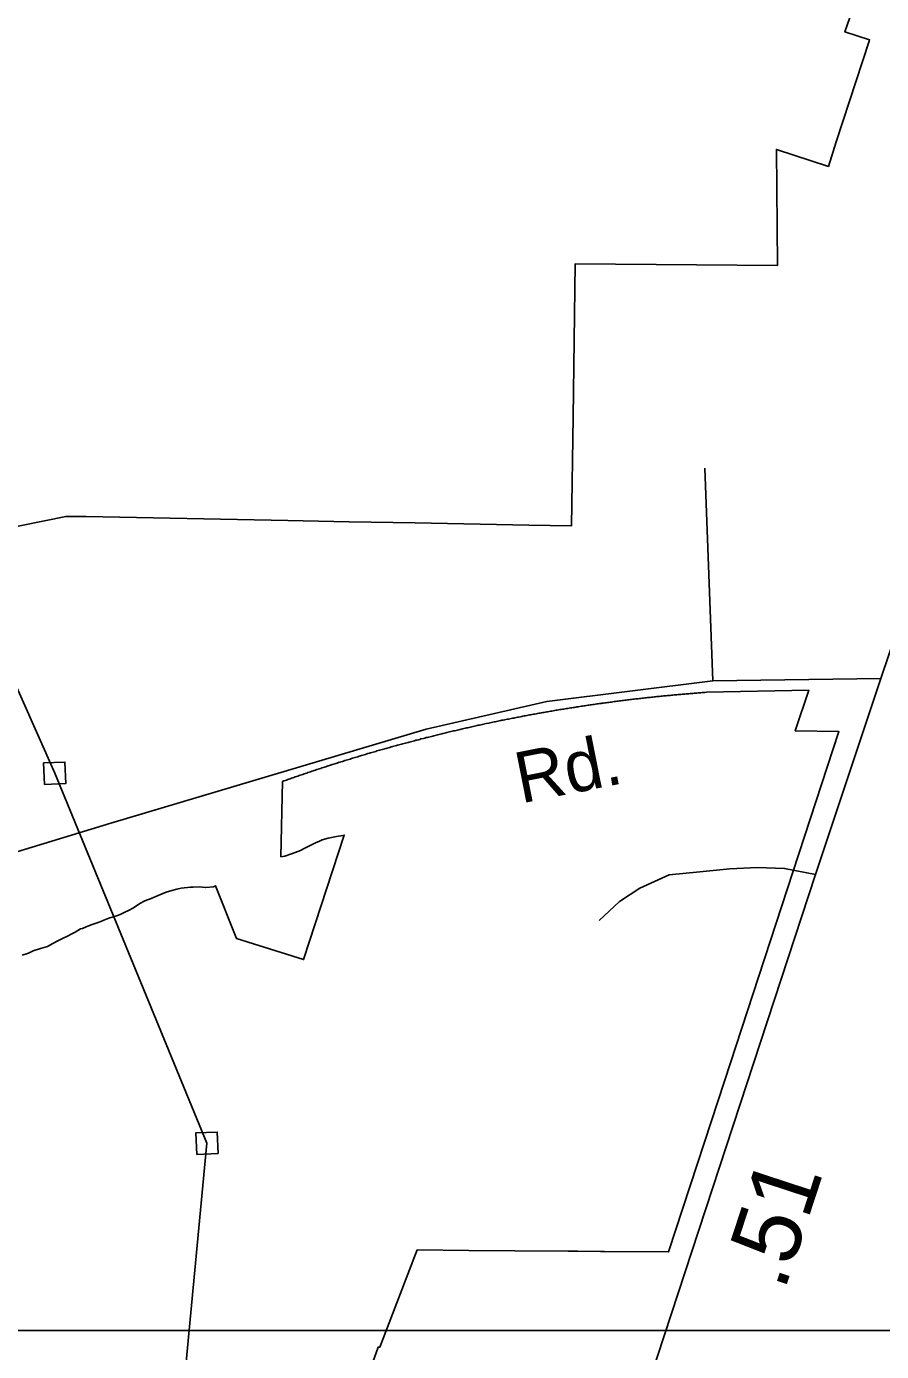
# Model space of a CAD drawing. Extents: x 2220236 to 2384410, y 720751 to 894131.
# Drawn here: x 2349968 to 2351563, y 785007 to 787479 of the extents above; entities that cross this region are included whole.
import ezdxf

# ---------------------------------------------------------------- set-up
doc = ezdxf.new("R2010")
doc.units = 0
doc.layers.add('Default', color=7, linetype='Continuous')

msp = doc.modelspace()

# ---------------------------------------------------------------- linework, layer by layer
at = {"layer": 'Default'}
msp.add_line((2351248.7, 786258.7), (2351233.6, 786655.1), dxfattribs=at)
for points in [[(2329807.7, 816974.9), (2370566.3, 816974.8), (2370566.3, 785046.7), (2329807.6, 785046.7), (2329807.7, 816974.9)], [(2350869.9, 782495.5), (2350436.8, 783070.4), (2350101.5, 783514.1), (2350174, 784150.7), (2350246.2, 784777.5), (2350304.8, 785395.9), (2350020.7, 786086.2), (2349800.8, 786581.5), (2349578.7, 787102.6), (2349360.6, 787617.7), (2349132.2, 788154.8), (2348908.1, 788664.1), (2348869.5, 789213.3), (2348832.1, 789830.7), (2348791.1, 790408), (2348767.9, 790843.5), (2348707.3, 791564.5), (2348681.9, 792186.1)], [(2351562, 786262.8), (2351799.1, 786963.7), (2351989.4, 787562.6), (2352125.4, 787964.9), (2352181.4, 788133.8), (2352264.4, 788402.1), (2352402.7, 788810.6), (2352509.2, 789143.1), (2352616.4, 789474.3), (2352724.5, 789807.5), (2352833.5, 790143.2), (2353000.4, 790646)], [(2349752.8, 786506.5), (2350041.2, 786565.4), (2350075.2, 786564.9), (2350079.2, 786564.9), (2350456, 786557.6), (2350570.2, 786555.4), (2350693.5, 786553.1), (2350905.5, 786549), (2350984.8, 786547.5), (2350988.2, 786750.3), (2350992, 787036.6), (2351369, 787033.2), (2351367.2, 787250.1), (2351464.2, 787218.4), (2351479, 787264.2), (2351540.5, 787452.1), (2351541.2, 787454.5), (2351495.2, 787469.2), (2351533, 787579.1)], [(2349752.8, 786506.5), (2350041.2, 786565.4), (2350075.2, 786564.9), (2350079.2, 786564.9), (2350456, 786557.6), (2350570.2, 786555.4), (2350693.5, 786553.1), (2350905.5, 786549), (2350984.8, 786547.5), (2350988.2, 786750.3), (2350992, 787036.6), (2351369, 787033.2), (2351367.2, 787250.1), (2351464.2, 787218.4), (2351479, 787264.2), (2351540.5, 787452.1), (2351541.2, 787454.5), (2351495.2, 787469.2), (2351533, 787579.1)], [(2347439.5, 785590.9), (2348148.9, 785589.9), (2348375.2, 785586.7), (2348691.9, 785588.9), (2348756.3, 785590.8), (2348812.8, 785598.7), (2348858.9, 785604.4), (2349766.1, 785883.8), (2350125.4, 785993), (2350713.5, 786168.5), (2350938.9, 786219.8), (2351248.7, 786258.7), (2351562, 786262.8)], [(2349423.6, 779733.7), (2349826, 780958.2), (2350004.8, 781494.8), (2350260.7, 782295.8), (2350506.4, 783037.3), (2351081.3, 784803.5), (2351440.4, 785897.5), (2351562, 786262.8)], [(2350697.2, 785196.8), (2350793.2, 785196.1), (2350879, 785195.4), (2350978.5, 785194.7), (2350996.8, 785194.6), (2351039, 785194.2), (2351046.5, 785194.2), (2351166, 785193.3), (2351233, 785398.1), (2351270.2, 785511.9), (2351483.8, 786164), (2351402.5, 786165.4), (2351427.5, 786241.4), (2351237, 786237.2), (2351233.8, 786236.9), (2351231.2, 786236.8), (2351228.8, 786236.6), (2351226.2, 786236.4), (2351223.8, 786236.2), (2351221.2, 786236), (2351218.8, 786235.8), (2351216.2, 786235.6), (2351213.8, 786235.4), (2351211.2, 786235.2), (2351208.8, 786235), (2351206.2, 786234.8), (2351203.8, 786234.6), (2351201.2, 786234.4), (2351199, 786234.2), (2351196.5, 786234), (2351194, 786233.8), (2351191.5, 786233.6), (2351189, 786233.3), (2351186.5, 786233.1), (2351184, 786232.9), (2351181.5, 786232.7), (2351179, 786232.4), (2351176.5, 786232.2), (2351174, 786232), (2351171.5, 786231.8), (2351169, 786231.5), (2351166.5, 786231.2), (2351164, 786231.1), (2351161.5, 786230.8), (2351159, 786230.6), (2351156.5, 786230.3), (2351154, 786230.1), (2351151.5, 786229.8), (2351149, 786229.6), (2351146.5, 786229.3), (2351144, 786229.1), (2351141.8, 786228.8), (2351139.2, 786228.6), (2351136.8, 786228.2), (2351134.2, 786228), (2351131.8, 786227.8), (2351129.2, 786227.5), (2351126.8, 786227.2), (2351124.2, 786226.9), (2351121.8, 786226.6), (2351119.2, 786226.4), (2351116.8, 786226.1), (2351114.2, 786225.8), (2351111.8, 786225.6), (2351109.2, 786225.2), (2351106.8, 786224.9), (2351104.2, 786224.7), (2351102, 786224.4), (2351099.5, 786224.1), (2351097, 786223.8), (2351094.5, 786223.5), (2351092, 786223.2), (2351089.5, 786222.9), (2351087, 786222.6), (2351084.5, 786222.3), (2351082, 786222), (2351079.5, 786221.7), (2351077, 786221.4), (2351074.5, 786221.1), (2351072, 786220.8), (2351069.5, 786220.4), (2351067.2, 786220.1), (2351064.8, 786219.8), (2351062.2, 786219.4), (2351059.8, 786219.1), (2351057.2, 786218.8), (2351054.8, 786218.4), (2351052.2, 786218.1), (2351049.8, 786217.8), (2351047.2, 786217.4), (2351044.8, 786217.1), (2351042.2, 786216.8), (2351040, 786216.4), (2351037.5, 786216.1), (2351035, 786215.8), (2351032.5, 786215.4), (2351030, 786215.1), (2351027.5, 786214.7), (2351025, 786214.3), (2351022.5, 786214), (2351020, 786213.6), (2351017.5, 786213.2), (2351015.2, 786212.9), (2351012.8, 786212.5), (2351010.2, 786212.2), (2351007.8, 786211.8), (2351005.2, 786211.4), (2351002.8, 786211.1), (2351000.2, 786210.7), (2350997.8, 786210.3), (2350995.2, 786209.9), (2350993, 786209.5), (2350990.5, 786209.1), (2350988, 786208.8), (2350985.5, 786208.4), (2350983, 786208), (2350980.5, 786207.6), (2350978, 786207.2), (2350975.5, 786206.8), (2350973.2, 786206.4), (2350970.8, 786206), (2350968.2, 786205.6), (2350965.8, 786205.2), (2350963.2, 786204.8), (2350960.8, 786204.4), (2350958.2, 786203.9), (2350956, 786203.6), (2350953.5, 786203.1), (2350951, 786202.7), (2350948.5, 786202.3), (2350946, 786201.9), (2350943.5, 786201.4), (2350941, 786201), (2350938.8, 786200.6), (2350936.2, 786200.2), (2350933.8, 786199.8), (2350931.2, 786199.3), (2350928.8, 786198.9), (2350926.2, 786198.4), (2350923.8, 786198), (2350921.5, 786197.6), (2350919, 786197.1), (2350916.5, 786196.7), (2350914, 786196.2), (2350911.5, 786195.8), (2350909, 786195.3), (2350906.8, 786194.9), (2350904.2, 786194.4), (2350901.8, 786193.9), (2350899.2, 786193.5), (2350896.8, 786193), (2350894.2, 786192.6), (2350892, 786192.1), (2350889.5, 786191.6), (2350887, 786191.1), (2350884.5, 786190.7), (2350882, 786190.2), (2350879.5, 786189.8), (2350877.2, 786189.2), (2350874.8, 786188.8), (2350872.2, 786188.3), (2350867.2, 786187.3), (2350865, 786186.8), (2350860, 786185.8), (2350857.5, 786185.4), (2350855, 786184.9), (2350852.8, 786184.4), (2350850.2, 786183.9), (2350847.8, 786183.3), (2350842.8, 786182.3), (2350840.5, 786181.8), (2350835.5, 786180.8), (2350833, 786180.3), (2350830.8, 786179.8), (2350825.8, 786178.8), (2350823.2, 786178.2), (2350820.8, 786177.7), (2350818.5, 786177.1), (2350816, 786176.6), (2350813.5, 786176.1), (2350811, 786175.6), (2350808.8, 786175), (2350806.2, 786174.5), (2350803.8, 786173.9), (2350801.2, 786173.4), (2350798.8, 786172.9), (2350796.5, 786172.3), (2350794, 786171.8), (2350791.5, 786171.2), (2350789, 786170.6), (2350786.8, 786170.1), (2350784.2, 786169.6), (2350781.8, 786169), (2350779.2, 786168.4), (2350777, 786167.9), (2350774.5, 786167.3), (2350772, 786166.8), (2350769.8, 786166.2), (2350767.2, 786165.6), (2350764.8, 786165), (2350762.2, 786164.4), (2350760, 786163.9), (2350757.5, 786163.3), (2350755, 786162.7), (2350752.5, 786162.1), (2350750.2, 786161.6), (2350747.8, 786160.9), (2350745.2, 786160.4), (2350743, 786159.8), (2350740.5, 786159.2), (2350738, 786158.6), (2350735.5, 786158), (2350733.2, 786157.4), (2350730.8, 786156.8), (2350728.2, 786156.2), (2350726, 786155.6), (2350723.5, 786155), (2350718.5, 786153.8), (2350716.2, 786153.1), (2350713.8, 786152.6), (2350711.2, 786151.9), (2350709, 786151.3), (2350704, 786150.1), (2350701.8, 786149.4), (2350696.8, 786148.2), (2350694.5, 786147.6), (2350692, 786146.9), (2350689.5, 786146.2), (2350686.8, 786145.5), (2350682.2, 786144.4), (2350680, 786143.7), (2350675, 786142.4), (2350672.8, 786141.8), (2350670.2, 786141.1), (2350667.8, 786140.4), (2350665.5, 786139.8), (2350663, 786139.1), (2350660.5, 786138.5), (2350658.2, 786137.8), (2350655.8, 786137.2), (2350653.2, 786136.5), (2350651, 786135.8), (2350648.5, 786135.2), (2350646.2, 786134.5), (2350643.8, 786133.8), (2350641.2, 786133.1), (2350639, 786132.4), (2350636.5, 786131.8), (2350634, 786131.1), (2350631.8, 786130.4), (2350629.2, 786129.8), (2350627, 786129.1), (2350624.5, 786128.4), (2350622, 786127.7), (2350619.8, 786127), (2350617.2, 786126.2), (2350615, 786125.6), (2350612.5, 786124.9), (2350610, 786124.2), (2350607.8, 786123.5), (2350605.2, 786122.8), (2350603, 786122.1), (2350600.5, 786121.4), (2350598, 786120.6), (2350595.8, 786119.9), (2350593.2, 786119.2), (2350591, 786118.5), (2350588.5, 786117.8), (2350586, 786117.1), (2350583.8, 786116.3), (2350581.2, 786115.6), (2350579, 786114.9), (2350576.5, 786114.1), (2350574.2, 786113.4), (2350571.8, 786112.7), (2350569.5, 786111.9), (2350567, 786111.2), (2350564.5, 786110.5), (2350562.2, 786109.8), (2350559.8, 786109), (2350557.5, 786108.2), (2350555, 786107.5), (2350552.8, 786106.8), (2350550.2, 786106), (2350548, 786105.2), (2350545.5, 786104.5), (2350543.2, 786103.8), (2350540.8, 786102.9), (2350538.5, 786102.2), (2350533.5, 786100.7), (2350531.2, 786099.9), (2350528.8, 786099.1), (2350526.5, 786098.4), (2350524, 786097.6), (2350521.8, 786096.8), (2350519.2, 786096.1), (2350517, 786095.2), (2350514.5, 786094.5), (2350512.2, 786093.7), (2350509.8, 786092.9), (2350507.5, 786092.1), (2350505, 786091.3), (2350502.8, 786090.6), (2350500.2, 786089.8), (2350498, 786088.9), (2350495.8, 786088.2), (2350493.2, 786087.4), (2350491, 786086.6), (2350488.5, 786085.8), (2350486.2, 786084.9), (2350483.8, 786084.1), (2350481.5, 786083.3), (2350479, 786082.5), (2350476.8, 786081.7), (2350474.2, 786080.9), (2350472, 786080.1), (2350469.5, 786079.2), (2350467.2, 786078.4), (2350465, 786077.6), (2350462.5, 786076.8), (2350460.2, 786075.9), (2350457.8, 786075.1), (2350455.5, 786074.3), (2350453, 786073.5), (2350450.8, 786072.6), (2350448.5, 786071.8), (2350445.8, 786071), (2350442.8, 785930.4), (2350449.8, 785931.6), (2350460.8, 785934.9), (2350469.5, 785938.2), (2350479.5, 785942.3), (2350484.8, 785945.3), (2350497.5, 785951.4), (2350507.5, 785956.2), (2350514.5, 785959.4), (2350519.5, 785961.8), (2350530.8, 785964.8), (2350546.8, 785968.3), (2350558.2, 785970.2), (2350561, 785970.9), (2350485, 785738.6), (2350359.8, 785777.6), (2350320.5, 785876.4), (2350316.8, 785874.1), (2350303, 785873.1), (2350301.8, 785872.9), (2350296.2, 785873.6), (2350290.8, 785874.1), (2350279.2, 785873.9), (2350274.2, 785873.9), (2350256.8, 785871.9), (2350248.5, 785870.1), (2350239.5, 785867.7), (2350228.8, 785864.2), (2350214, 785858.2), (2350201, 785852.8), (2350189.2, 785848.4), (2350179.5, 785843.1), (2350167.8, 785835.2), (2350158.5, 785830.2), (2350151.8, 785827.1), (2350142.8, 785822.9), (2350137.8, 785820.8), (2350121.5, 785815.6), (2350112.2, 785812.3), (2350106.8, 785809.8), (2350100, 785807.2), (2350090.5, 785803.9), (2350082.8, 785800.9), (2350079.2, 785799.6), (2350072.5, 785796.4), (2350069, 785795.8), (2350058.8, 785789.8), (2350050.2, 785785.6), (2350046, 785782.9), (2350035.2, 785777.9), (2350025.5, 785773.1), (2350017.2, 785768.5), (2350007, 785762.8), (2349994.5, 785759.3), (2349980.5, 785754.8), (2349972, 785750.8), (2349960, 785747)], [(2350697.2, 785196.8), (2350793.2, 785196.1), (2350879, 785195.4), (2350978.5, 785194.7), (2350996.8, 785194.6), (2351039, 785194.2), (2351046.5, 785194.2), (2351166, 785193.3), (2351233, 785398.1), (2351270.2, 785511.9), (2351483.8, 786164), (2351402.5, 786165.4), (2351427.5, 786241.4), (2351237, 786237.2), (2351233.8, 786236.9), (2351231.2, 786236.8), (2351228.8, 786236.6), (2351226.2, 786236.4), (2351223.8, 786236.2), (2351221.2, 786236), (2351218.8, 786235.8), (2351216.2, 786235.6), (2351213.8, 786235.4), (2351211.2, 786235.2), (2351208.8, 786235), (2351206.2, 786234.8), (2351203.8, 786234.6), (2351201.2, 786234.4), (2351199, 786234.2), (2351196.5, 786234), (2351194, 786233.8), (2351191.5, 786233.6), (2351189, 786233.3), (2351186.5, 786233.1), (2351184, 786232.9), (2351181.5, 786232.7), (2351179, 786232.4), (2351176.5, 786232.2), (2351174, 786232), (2351171.5, 786231.8), (2351169, 786231.5), (2351166.5, 786231.2), (2351164, 786231.1), (2351161.5, 786230.8), (2351159, 786230.6), (2351156.5, 786230.3), (2351154, 786230.1), (2351151.5, 786229.8), (2351149, 786229.6), (2351146.5, 786229.3), (2351144, 786229.1), (2351141.8, 786228.8), (2351139.2, 786228.6), (2351136.8, 786228.2), (2351134.2, 786228), (2351131.8, 786227.8), (2351129.2, 786227.5), (2351126.8, 786227.2), (2351124.2, 786226.9), (2351121.8, 786226.6), (2351119.2, 786226.4), (2351116.8, 786226.1), (2351114.2, 786225.8), (2351111.8, 786225.6), (2351109.2, 786225.2), (2351106.8, 786224.9), (2351104.2, 786224.7), (2351102, 786224.4), (2351099.5, 786224.1), (2351097, 786223.8), (2351094.5, 786223.5), (2351092, 786223.2), (2351089.5, 786222.9), (2351087, 786222.6), (2351084.5, 786222.3), (2351082, 786222), (2351079.5, 786221.7), (2351077, 786221.4), (2351074.5, 786221.1), (2351072, 786220.8), (2351069.5, 786220.4), (2351067.2, 786220.1), (2351064.8, 786219.8), (2351062.2, 786219.4), (2351059.8, 786219.1), (2351057.2, 786218.8), (2351054.8, 786218.4), (2351052.2, 786218.1), (2351049.8, 786217.8), (2351047.2, 786217.4), (2351044.8, 786217.1), (2351042.2, 786216.8), (2351040, 786216.4), (2351037.5, 786216.1), (2351035, 786215.8), (2351032.5, 786215.4), (2351030, 786215.1), (2351027.5, 786214.7), (2351025, 786214.3), (2351022.5, 786214), (2351020, 786213.6), (2351017.5, 786213.2), (2351015.2, 786212.9), (2351012.8, 786212.5), (2351010.2, 786212.2), (2351007.8, 786211.8), (2351005.2, 786211.4), (2351002.8, 786211.1), (2351000.2, 786210.7), (2350997.8, 786210.3), (2350995.2, 786209.9), (2350993, 786209.5), (2350990.5, 786209.1), (2350988, 786208.8), (2350985.5, 786208.4), (2350983, 786208), (2350980.5, 786207.6), (2350978, 786207.2), (2350975.5, 786206.8), (2350973.2, 786206.4), (2350970.8, 786206), (2350968.2, 786205.6), (2350965.8, 786205.2), (2350963.2, 786204.8), (2350960.8, 786204.4), (2350958.2, 786203.9), (2350956, 786203.6), (2350953.5, 786203.1), (2350951, 786202.7), (2350948.5, 786202.3), (2350946, 786201.9), (2350943.5, 786201.4), (2350941, 786201), (2350938.8, 786200.6), (2350936.2, 786200.2), (2350933.8, 786199.8), (2350931.2, 786199.3), (2350928.8, 786198.9), (2350926.2, 786198.4), (2350923.8, 786198), (2350921.5, 786197.6), (2350919, 786197.1), (2350916.5, 786196.7), (2350914, 786196.2), (2350911.5, 786195.8), (2350909, 786195.3), (2350906.8, 786194.9), (2350904.2, 786194.4), (2350901.8, 786193.9), (2350899.2, 786193.5), (2350896.8, 786193), (2350894.2, 786192.6), (2350892, 786192.1), (2350889.5, 786191.6), (2350887, 786191.1), (2350884.5, 786190.7), (2350882, 786190.2), (2350879.5, 786189.8), (2350877.2, 786189.2), (2350874.8, 786188.8), (2350872.2, 786188.3), (2350867.2, 786187.3), (2350865, 786186.8), (2350860, 786185.8), (2350857.5, 786185.4), (2350855, 786184.9), (2350852.8, 786184.4), (2350850.2, 786183.9), (2350847.8, 786183.3), (2350842.8, 786182.3), (2350840.5, 786181.8), (2350835.5, 786180.8), (2350833, 786180.3), (2350830.8, 786179.8), (2350825.8, 786178.8), (2350823.2, 786178.2), (2350820.8, 786177.7), (2350818.5, 786177.1), (2350816, 786176.6), (2350813.5, 786176.1), (2350811, 786175.6), (2350808.8, 786175), (2350806.2, 786174.5), (2350803.8, 786173.9), (2350801.2, 786173.4), (2350798.8, 786172.9), (2350796.5, 786172.3), (2350794, 786171.8), (2350791.5, 786171.2), (2350789, 786170.6), (2350786.8, 786170.1), (2350784.2, 786169.6), (2350781.8, 786169), (2350779.2, 786168.4), (2350777, 786167.9), (2350774.5, 786167.3), (2350772, 786166.8), (2350769.8, 786166.2), (2350767.2, 786165.6), (2350764.8, 786165), (2350762.2, 786164.4), (2350760, 786163.9), (2350757.5, 786163.3), (2350755, 786162.7), (2350752.5, 786162.1), (2350750.2, 786161.6), (2350747.8, 786160.9), (2350745.2, 786160.4), (2350743, 786159.8), (2350740.5, 786159.2), (2350738, 786158.6), (2350735.5, 786158), (2350733.2, 786157.4), (2350730.8, 786156.8), (2350728.2, 786156.2), (2350726, 786155.6), (2350723.5, 786155), (2350718.5, 786153.8), (2350716.2, 786153.1), (2350713.8, 786152.6), (2350711.2, 786151.9), (2350709, 786151.3), (2350704, 786150.1), (2350701.8, 786149.4), (2350696.8, 786148.2), (2350694.5, 786147.6), (2350692, 786146.9), (2350689.5, 786146.2), (2350686.8, 786145.5), (2350682.2, 786144.4), (2350680, 786143.7), (2350675, 786142.4), (2350672.8, 786141.8), (2350670.2, 786141.1), (2350667.8, 786140.4), (2350665.5, 786139.8), (2350663, 786139.1), (2350660.5, 786138.5), (2350658.2, 786137.8), (2350655.8, 786137.2), (2350653.2, 786136.5), (2350651, 786135.8), (2350648.5, 786135.2), (2350646.2, 786134.5), (2350643.8, 786133.8), (2350641.2, 786133.1), (2350639, 786132.4), (2350636.5, 786131.8), (2350634, 786131.1), (2350631.8, 786130.4), (2350629.2, 786129.8), (2350627, 786129.1), (2350624.5, 786128.4), (2350622, 786127.7), (2350619.8, 786127), (2350617.2, 786126.2), (2350615, 786125.6), (2350612.5, 786124.9), (2350610, 786124.2), (2350607.8, 786123.5), (2350605.2, 786122.8), (2350603, 786122.1), (2350600.5, 786121.4), (2350598, 786120.6), (2350595.8, 786119.9), (2350593.2, 786119.2), (2350591, 786118.5), (2350588.5, 786117.8), (2350586, 786117.1), (2350583.8, 786116.3), (2350581.2, 786115.6), (2350579, 786114.9), (2350576.5, 786114.1), (2350574.2, 786113.4), (2350571.8, 786112.7), (2350569.5, 786111.9), (2350567, 786111.2), (2350564.5, 786110.5), (2350562.2, 786109.8), (2350559.8, 786109), (2350557.5, 786108.2), (2350555, 786107.5), (2350552.8, 786106.8), (2350550.2, 786106), (2350548, 786105.2), (2350545.5, 786104.5), (2350543.2, 786103.8), (2350540.8, 786102.9), (2350538.5, 786102.2), (2350533.5, 786100.7), (2350531.2, 786099.9), (2350528.8, 786099.1), (2350526.5, 786098.4), (2350524, 786097.6), (2350521.8, 786096.8), (2350519.2, 786096.1), (2350517, 786095.2), (2350514.5, 786094.5), (2350512.2, 786093.7), (2350509.8, 786092.9), (2350507.5, 786092.1), (2350505, 786091.3), (2350502.8, 786090.6), (2350500.2, 786089.8), (2350498, 786088.9), (2350495.8, 786088.2), (2350493.2, 786087.4), (2350491, 786086.6), (2350488.5, 786085.8), (2350486.2, 786084.9), (2350483.8, 786084.1), (2350481.5, 786083.3), (2350479, 786082.5), (2350476.8, 786081.7), (2350474.2, 786080.9), (2350472, 786080.1), (2350469.5, 786079.2), (2350467.2, 786078.4), (2350465, 786077.6), (2350462.5, 786076.8), (2350460.2, 786075.9), (2350457.8, 786075.1), (2350455.5, 786074.3), (2350453, 786073.5), (2350450.8, 786072.6), (2350448.5, 786071.8), (2350445.8, 786071), (2350442.8, 785930.4), (2350449.8, 785931.6), (2350460.8, 785934.9), (2350469.5, 785938.2), (2350479.5, 785942.3), (2350484.8, 785945.3), (2350497.5, 785951.4), (2350507.5, 785956.2), (2350514.5, 785959.4), (2350519.5, 785961.8), (2350530.8, 785964.8), (2350546.8, 785968.3), (2350558.2, 785970.2), (2350561, 785970.9), (2350485, 785738.6), (2350359.8, 785777.6), (2350320.5, 785876.4), (2350316.8, 785874.1), (2350303, 785873.1), (2350301.8, 785872.9), (2350296.2, 785873.6), (2350290.8, 785874.1), (2350279.2, 785873.9), (2350274.2, 785873.9), (2350256.8, 785871.9), (2350248.5, 785870.1), (2350239.5, 785867.7), (2350228.8, 785864.2), (2350214, 785858.2), (2350201, 785852.8), (2350189.2, 785848.4), (2350179.5, 785843.1), (2350167.8, 785835.2), (2350158.5, 785830.2), (2350151.8, 785827.1), (2350142.8, 785822.9), (2350137.8, 785820.8), (2350121.5, 785815.6), (2350112.2, 785812.3), (2350106.8, 785809.8), (2350100, 785807.2), (2350090.5, 785803.9), (2350082.8, 785800.9), (2350079.2, 785799.6), (2350072.5, 785796.4), (2350069, 785795.8), (2350058.8, 785789.8), (2350050.2, 785785.6), (2350046, 785782.9), (2350035.2, 785777.9), (2350025.5, 785773.1), (2350017.2, 785768.5), (2350007, 785762.8), (2349994.5, 785759.3), (2349980.5, 785754.8), (2349972, 785750.8), (2349960, 785747)], [(2350001.6, 786065.4), (2350041.5, 786067.1), (2350039.9, 786107), (2350000, 786105.4), (2350001.6, 786065.4)], [(2351036.5, 785811.2), (2351074.4, 785847.2), (2351112.3, 785871.8), (2351167.2, 785896.5), (2351224.1, 785902.2), (2351280.4, 785907.6), (2351332.3, 785910.1), (2351382.4, 785908.7), (2351440.4, 785897.5)], [(2350285.7, 785375.1), (2350325.6, 785376.8), (2350324, 785416.7), (2350284, 785415.1), (2350285.7, 785375.1)], [(2350851.2, 782618.4), (2351157, 783556.1), (2350820.5, 783666.4), (2350769, 783682.6), (2350676.5, 783714), (2350678.2, 783718.9), (2350731.2, 783879.1), (2350816.2, 784135.9), (2350879.8, 784327.2), (2350943.2, 784518.6), (2351045.5, 784827.2), (2350920.5, 784828.3), (2350577.5, 784831.3), (2350559.2, 784831.9), (2350624.2, 785015.2), (2350627.2, 785015.2), (2350697.2, 785196.8)], [(2350851.2, 782618.4), (2351157, 783556.1), (2350820.5, 783666.4), (2350769, 783682.6), (2350676.5, 783714), (2350678.2, 783718.9), (2350731.2, 783879.1), (2350816.2, 784135.9), (2350879.8, 784327.2), (2350943.2, 784518.6), (2351045.5, 784827.2), (2350920.5, 784828.3), (2350577.5, 784831.3), (2350559.2, 784831.9), (2350624.2, 785015.2), (2350627.2, 785015.2), (2350697.2, 785196.8)]]:
    msp.add_lwpolyline(points, dxfattribs=at)

# ---------------------------------------------------------------- texts
for s, height, rotation, p in [('Rd.', 95, 11.2322, (2350890.5, 786029.6)), ('.51', 125, 71.8294, (2351382.1, 785118.6))]:
    msp.add_text(s, height=height, rotation=rotation, dxfattribs=at).set_placement(p)

doc.saveas('drawing.dxf')
